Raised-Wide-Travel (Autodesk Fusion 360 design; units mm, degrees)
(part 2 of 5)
work_plane "WorkPlane28" AlongDistance 15.3 ExtraOffset 0
sketch "Fill former insert location (3)" plane through (15.3, 0, 0) normal (1, 0, 0) x axis (0, 0, -1)
  circle C1 centre (-52, -51) radius 2.01
extrude "Extrude28" add sketch "Fill former insert location (3)" along normal blind 8.7
work_plane "WorkPlane27" AlongDistance -36 ExtraOffset 0
sketch "Fill former plate mounting hole (1)" plane through (-36, 0, 0) normal (1, 0, 0) x axis (0, 0, -1)
  circle C1 centre (-52, -51) radius 1.71
extrude "Extrude27" add sketch "Fill former plate mounting hole (1)" along normal blind 12
work_plane "WorkPlane26" AlongDistance 24 ExtraOffset 0
sketch "Fill former plate mounting hole (1)" plane through (24, 0, 0) normal (1, 0, 0) x axis (0, 0, -1)
  circle C1 centre (-52, -51) radius 1.71
extrude "Extrude26" add sketch "Fill former plate mounting hole (1)" along normal blind 12
work_plane "WorkPlane29" AlongDistance -24.1 ExtraOffset 0
sketch "Relocated insert with cam-side retaining wall" plane through (-24.1, 0, 0) normal (1, 0, 0) x axis (0, 0, -1)
  circle C1 centre (-53.5, -62) radius 2
extrude "Extrude29" cut sketch "Relocated insert with cam-side retaining wall" along normal blind 8.9
work_plane "WorkPlane30" AlongDistance 15.3 ExtraOffset 0
sketch "Relocated insert with cam-side retaining wall (1)" plane through (15.3, 0, 0) normal (1, 0, 0) x axis (0, 0, -1)
  circle C1 centre (-53.5, -62) radius 2
extrude "Extrude30" cut sketch "Relocated insert with cam-side retaining wall (1)" along normal blind 8.9
work_plane "WorkPlane28" AlongDistance -36.1 ExtraOffset 0
sketch "Relocated mount above rail counterbore" plane through (-36.1, 0, 0) normal (1, 0, 0) x axis (0, 0, -1)
  circle C1 centre (-53.5, -62) radius 1.7
extrude "Extrude28" cut sketch "Relocated mount above rail counterbore" along normal blind 12.2
work_plane "WorkPlane27" AlongDistance 23.9 ExtraOffset 0
sketch "Relocated mount above rail counterbore" plane through (23.9, 0, 0) normal (1, 0, 0) x axis (0, 0, -1)
  circle C1 centre (-53.5, -62) radius 1.7
extrude "Extrude27" cut sketch "Relocated mount above rail counterbore" along normal blind 12.2
work_plane "WorkPlane31" AlongDistance -24.1 ExtraOffset 0
sketch "Relocated insert with cam-side retaining wall (2)" plane through (-24.1, 0, 0) normal (1, 0, 0) x axis (0, 0, -1)
  circle C1 centre (-53.5, -54) radius 2
extrude "Extrude31" cut sketch "Relocated insert with cam-side retaining wall (2)" along normal blind 8.9
work_plane "WorkPlane32" AlongDistance 15.3 ExtraOffset 0
sketch "Relocated insert with cam-side retaining wall (3)" plane through (15.3, 0, 0) normal (1, 0, 0) x axis (0, 0, -1)
  circle C1 centre (-53.5, -54) radius 2
extrude "Extrude32" cut sketch "Relocated insert with cam-side retaining wall (3)" along normal blind 8.9
work_plane "WorkPlane29" AlongDistance -36.1 ExtraOffset 0
sketch "Relocated mount above rail counterbore (1)" plane through (-36.1, 0, 0) normal (1, 0, 0) x axis (0, 0, -1)
  circle C1 centre (-53.5, -54) radius 1.7
extrude "Extrude29" cut sketch "Relocated mount above rail counterbore (1)" along normal blind 12.2
work_plane "WorkPlane28" AlongDistance 23.9 ExtraOffset 0
sketch "Relocated mount above rail counterbore (1)" plane through (23.9, 0, 0) normal (1, 0, 0) x axis (0, 0, -1)
  circle C1 centre (-53.5, -54) radius 1.7
extrude "Extrude28" cut sketch "Relocated mount above rail counterbore (1)" along normal blind 12.2
work_plane "WorkPlane33" AlongDistance 51.9 ExtraOffset 0
sketch "Continue adjuster bore through roof" plane through (0, 0, 51.9) normal (0, 0, 1) x axis (1, 0, 0)
  circle C1 centre (12, -55) radius 2.2
extrude "Extrude33" cut sketch "Continue adjuster bore through roof" along normal blind 7.2
work_plane "WorkPlane34" AlongDistance 51.9 ExtraOffset 0
sketch "Continue guide bore through roof" plane through (0, 0, 51.9) normal (0, 0, 1) x axis (1, 0, 0)
  circle C1 centre (5, -55) radius 1.7
extrude "Extrude34" cut sketch "Continue guide bore through roof" along normal blind 7.2
work_plane "WorkPlane35" AlongDistance 51.9 ExtraOffset 0
sketch "Continue guide bore through roof (1)" plane through (0, 0, 51.9) normal (0, 0, 1) x axis (1, 0, 0)
  circle C1 centre (19, -55) radius 1.7
extrude "Extrude35" cut sketch "Continue guide bore through roof (1)" along normal blind 7.2
work_plane "WorkPlane36" AlongDistance -24.1 ExtraOffset 0
sketch "Restore cam envelope after pocket repair" plane through (-24.1, 0, 0) normal (1, 0, 0) x axis (0, 0, -1)
  circle C1 centre (-65, 0) radius 51
extrude "Extrude36" cut sketch "Restore cam envelope after pocket repair" along normal blind 48.2
work_plane "WorkPlane30" AlongDistance -76 ExtraOffset 0
sketch "Preserve rail shank passage" plane through (0, -76, 0) normal (0, 1, 0) x axis (1, 0, 0)
  circle C1 centre (-30, -45) radius 2.7
work_plane "WorkPlane31" AlongDistance 54 ExtraOffset 0
sketch "Preserve rail shank passage (1)" plane through (0, 54, 0) normal (0, 1, 0) x axis (1, 0, 0)
  circle C1 centre (-30, -45) radius 2.7
work_plane "WorkPlane32" AlongDistance -55 ExtraOffset 0
sketch "Preserve rail head passage" plane through (0, -55, 0) normal (0, 1, 0) x axis (1, 0, 0)
  circle C1 centre (-30, -45) radius 5.3
extrude "Extrude32" cut sketch "Preserve rail head passage" along normal blind 12
work_plane "WorkPlane33" AlongDistance 43 ExtraOffset 0
sketch "Preserve rail head passage (1)" plane through (0, 43, 0) normal (0, 1, 0) x axis (1, 0, 0)
  circle C1 centre (-30, -45) radius 5.3
work_plane "WorkPlane29" AlongDistance -76 ExtraOffset 0
sketch "Preserve rail shank passage" plane through (0, -76, 0) normal (0, 1, 0) x axis (1, 0, 0)
  circle C1 centre (30, -45) radius 2.7
work_plane "WorkPlane30" AlongDistance 54 ExtraOffset 0
sketch "Preserve rail shank passage (1)" plane through (0, 54, 0) normal (0, 1, 0) x axis (1, 0, 0)
  circle C1 centre (30, -45) radius 2.7
work_plane "WorkPlane31" AlongDistance -55 ExtraOffset 0
sketch "Preserve rail head passage" plane through (0, -55, 0) normal (0, 1, 0) x axis (1, 0, 0)
  circle C1 centre (30, -45) radius 5.3
extrude "Extrude31" cut sketch "Preserve rail head passage" along normal blind 12
work_plane "WorkPlane32" AlongDistance 43 ExtraOffset 0
sketch "Preserve rail head passage (1)" plane through (0, 43, 0) normal (0, 1, 0) x axis (1, 0, 0)
  circle C1 centre (30, -45) radius 5.3
work_plane "WorkPlane16" AlongDistance -5 ExtraOffset 0
sketch "Flat washer seat for sensor-drive shaft clamp" plane through (-5, 0, 0) normal (1, 0, 0) x axis (0, 0, -1)
  line L1 (-60, 22) -> (-60, 20)
  line L2 (-70, 22) -> (-60, 22)
  line L3 (-70, 20) -> (-70, 22)
  line L4 (-60, 20) -> (-70, 20)
extrude "Extrude16" add sketch "Flat washer seat for sensor-drive shaft clamp" along normal blind 10
work_plane "WorkPlane17" AlongDistance 6.4 ExtraOffset 0
sketch "Radial screw onto printed shaft D flat" plane through (0, 6.4, 0) normal (0, 1, 0) x axis (1, 0, 0)
  circle C1 centre (0, -65) radius 1.7
extrude "Extrude17" cut sketch "Radial screw onto printed shaft D flat" along normal blind 15.7
work_plane "WorkPlane18" AlongDistance 15.2 ExtraOffset 0
sketch "M3 heatset pocket for rotor clamp" plane through (0, 15.2, 0) normal (0, 1, 0) x axis (1, 0, 0)
  circle C1 centre (0, -65) radius 2
extrude "Extrude18" cut sketch "M3 heatset pocket for rotor clamp" along normal blind 6.9
work_plane "WorkPlane37" AlongDistance -24 ExtraOffset 0
sketch "Extend reaction block into free rail bay" plane through (-24, 0, 0) normal (1, 0, 0) x axis (0, 0, -1)
  line L1 (-38, -66) -> (-38, -74)
  line L2 (-59, -66) -> (-38, -66)
  line L3 (-59, -74) -> (-59, -66)
  line L4 (-38, -74) -> (-59, -74)
extrude "Extrude37" add sketch "Extend reaction block into free rail bay" along normal blind 48
work_plane "WorkPlane38" AlongDistance -24 ExtraOffset 0
sketch "Close mounting bore that crossed cup guide" plane through (-24, 0, 0) normal (1, 0, 0) x axis (0, 0, -1)
  circle C1 centre (-53.5, -54) radius 2.01
extrude "Extrude38" add sketch "Close mounting bore that crossed cup guide" along normal blind 8.7
work_plane "WorkPlane39" AlongDistance -24.1 ExtraOffset 0
sketch "Outer mounting row clear of guide" plane through (-24.1, 0, 0) normal (1, 0, 0) x axis (0, 0, -1)
  circle C1 centre (-53.5, -70) radius 2
extrude "Extrude39" cut sketch "Outer mounting row clear of guide" along normal blind 8.9
work_plane "WorkPlane40" AlongDistance 15.3 ExtraOffset 0
sketch "Close mounting bore that crossed cup guide (1)" plane through (15.3, 0, 0) normal (1, 0, 0) x axis (0, 0, -1)
  circle C1 centre (-53.5, -54) radius 2.01
extrude "Extrude40" add sketch "Close mounting bore that crossed cup guide (1)" along normal blind 8.7
work_plane "WorkPlane41" AlongDistance 15.2 ExtraOffset 0
sketch "Outer mounting row clear of guide (1)" plane through (15.2, 0, 0) normal (1, 0, 0) x axis (0, 0, -1)
  circle C1 centre (-53.5, -70) radius 2
extrude "Extrude41" cut sketch "Outer mounting row clear of guide (1)" along normal blind 8.9
work_plane "WorkPlane34" AlongDistance -36 ExtraOffset 0
sketch "Close former inner mounting hole" plane through (-36, 0, 0) normal (1, 0, 0) x axis (0, 0, -1)
  circle C1 centre (-53.5, -54) radius 1.71
extrude "Extrude34" add sketch "Close former inner mounting hole" along normal blind 12
work_plane "WorkPlane35" AlongDistance -36.1 ExtraOffset 0
sketch "Matched outer mounting row" plane through (-36.1, 0, 0) normal (1, 0, 0) x axis (0, 0, -1)
  circle C1 centre (-53.5, -70) radius 1.7
extrude "Extrude35" cut sketch "Matched outer mounting row" along normal blind 12.2
work_plane "WorkPlane33" AlongDistance 24 ExtraOffset 0
sketch "Close former inner mounting hole" plane through (24, 0, 0) normal (1, 0, 0) x axis (0, 0, -1)
  circle C1 centre (-53.5, -54) radius 1.71
extrude "Extrude33" add sketch "Close former inner mounting hole" along normal blind 12
work_plane "WorkPlane34" AlongDistance 23.9 ExtraOffset 0
sketch "Matched outer mounting row" plane through (23.9, 0, 0) normal (1, 0, 0) x axis (0, 0, -1)
  circle C1 centre (-53.5, -70) radius 1.7
extrude "Extrude34" cut sketch "Matched outer mounting row" along normal blind 12.2
work_plane "WorkPlane42" AlongDistance 37.9 ExtraOffset 0
sketch "Restore separate cup guide bore" plane through (0, 0, 37.9) normal (0, 0, 1) x axis (1, 0, 0)
  circle C1 centre (5, -55) radius 1.7
work_plane "WorkPlane43" AlongDistance 37.9 ExtraOffset 0
sketch "Restore separate cup guide bore (1)" plane through (0, 0, 37.9) normal (0, 0, 1) x axis (1, 0, 0)
  circle C1 centre (19, -55) radius 1.7
extrude "Extrude43" cut sketch "Restore separate cup guide bore (1)" along normal blind 21.2
work_plane "WorkPlane44" AlongDistance -24.1 ExtraOffset 0
sketch "Preserve cam envelope" plane through (-24.1, 0, 0) normal (1, 0, 0) x axis (0, 0, -1)
  circle C1 centre (-65, 0) radius 51
work_plane "WorkPlane36" AlongDistance -55 ExtraOffset 0
sketch "Close inaccessible rail head pocket" plane through (0, -55, 0) normal (0, 1, 0) x axis (1, 0, 0)
  circle C1 centre (-30, -45) radius 5.31
extrude "Extrude36" add sketch "Close inaccessible rail head pocket" along normal blind 12
work_plane "WorkPlane37" AlongDistance 43 ExtraOffset 0
sketch "Close inaccessible rail head pocket (1)" plane through (0, 43, 0) normal (0, 1, 0) x axis (1, 0, 0)
  circle C1 centre (-30, -45) radius 5.31
extrude "Extrude37" add sketch "Close inaccessible rail head pocket (1)" along normal blind 12
work_plane "WorkPlane38" AlongDistance -75 ExtraOffset 0
sketch "Close obsolete side rail bore" plane through (0, -75, 0) normal (0, 1, 0) x axis (1, 0, 0)
  circle C1 centre (-30, -45) radius 2.71
extrude "Extrude38" add sketch "Close obsolete side rail bore" along normal blind 20
work_plane "WorkPlane39" AlongDistance 55 ExtraOffset 0
sketch "Close obsolete side rail bore (1)" plane through (0, 55, 0) normal (0, 1, 0) x axis (1, 0, 0)
  circle C1 centre (-30, -45) radius 2.71
extrude "Extrude39" add sketch "Close obsolete side rail bore (1)" along normal blind 20
work_plane "WorkPlane40" AlongDistance -36 ExtraOffset 0
sketch "Top-access 2020 mounting flange" plane through (-36, 0, 0) normal (1, 0, 0) x axis (0, 0, -1)
  line L1 (-55, -70) -> (-55, -95)
  line L2 (-63, -70) -> (-55, -70)
  line L3 (-63, -95) -> (-63, -70)
  line L4 (-55, -95) -> (-63, -95)
extrude "Extrude40" add sketch "Top-access 2020 mounting flange" along normal blind 12
work_plane "WorkPlane41" AlongDistance -36 ExtraOffset 0
sketch "Mount root triangular reinforcement" plane through (-36, 0, 0) normal (1, 0, 0) x axis (0, 0, -1)
  line L1 (-56, -63) -> (-56, -70)
  line L2 (-63, -70) -> (-56, -63)
  line L3 (-56, -70) -> (-63, -70)
extrude "Extrude41" add sketch "Mount root triangular reinforcement" along normal blind 12
work_plane "WorkPlane42" AlongDistance 54.9 ExtraOffset 0
sketch "Vertical M5 rail mounting bore" plane through (0, 0, 54.9) normal (0, 0, 1) x axis (1, 0, 0)
  circle C1 centre (-30, -85) radius 2.7
extrude "Extrude42" cut sketch "Vertical M5 rail mounting bore" along normal blind 8.2
work_plane "WorkPlane43" AlongDistance -36 ExtraOffset 0
sketch "Top-access 2020 mounting flange (1)" plane through (-36, 0, 0) normal (1, 0, 0) x axis (0, 0, -1)
  line L1 (-55, 95) -> (-55, 70)
  line L2 (-63, 95) -> (-55, 95)
  line L3 (-63, 70) -> (-63, 95)
  line L4 (-55, 70) -> (-63, 70)
extrude "Extrude43" add sketch "Top-access 2020 mounting flange (1)" along normal blind 12
work_plane "WorkPlane44" AlongDistance -36 ExtraOffset 0
sketch "Mount root triangular reinforcement (1)" plane through (-36, 0, 0) normal (1, 0, 0) x axis (0, 0, -1)
  line L1 (-56, 70) -> (-56, 63)
  line L2 (-63, 70) -> (-56, 70)
  line L3 (-56, 63) -> (-63, 70)
extrude "Extrude44" add sketch "Mount root triangular reinforcement (1)" along normal blind 12
work_plane "WorkPlane45" AlongDistance 54.9 ExtraOffset 0
sketch "Vertical M5 rail mounting bore (1)" plane through (0, 0, 54.9) normal (0, 0, 1) x axis (1, 0, 0)
  circle C1 centre (-30, 85) radius 2.7
extrude "Extrude45" cut sketch "Vertical M5 rail mounting bore (1)" along normal blind 8.2
work_plane "WorkPlane46" AlongDistance -36 ExtraOffset 0
sketch "Close old M5 pivot clearance" plane through (-36, 0, 0) normal (1, 0, 0) x axis (0, 0, -1)
  circle C1 centre (-12, -35) radius 2.71
extrude "Extrude46" add sketch "Close old M5 pivot clearance" along normal blind 12
work_plane "WorkPlane47" AlongDistance -36.1 ExtraOffset 0
sketch "M3 follower pivot clearance" plane through (-36.1, 0, 0) normal (1, 0, 0) x axis (0, 0, -1)
  circle C1 centre (-12, -35) radius 1.7
extrude "Extrude47" cut sketch "M3 follower pivot clearance" along normal blind 12.2
work_plane "WorkPlane35" AlongDistance -55 ExtraOffset 0
sketch "Close inaccessible rail head pocket" plane through (0, -55, 0) normal (0, 1, 0) x axis (1, 0, 0)
  circle C1 centre (30, -45) radius 5.31
extrude "Extrude35" add sketch "Close inaccessible rail head pocket" along normal blind 12
work_plane "WorkPlane36" AlongDistance 43 ExtraOffset 0
sketch "Close inaccessible rail head pocket (1)" plane through (0, 43, 0) normal (0, 1, 0) x axis (1, 0, 0)
  circle C1 centre (30, -45) radius 5.31
extrude "Extrude36" add sketch "Close inaccessible rail head pocket (1)" along normal blind 12
work_plane "WorkPlane37" AlongDistance -75 ExtraOffset 0
sketch "Close obsolete side rail bore" plane through (0, -75, 0) normal (0, 1, 0) x axis (1, 0, 0)
  circle C1 centre (30, -45) radius 2.71
extrude "Extrude37" add sketch "Close obsolete side rail bore" along normal blind 20
work_plane "WorkPlane38" AlongDistance 55 ExtraOffset 0
sketch "Close obsolete side rail bore (1)" plane through (0, 55, 0) normal (0, 1, 0) x axis (1, 0, 0)
  circle C1 centre (30, -45) radius 2.71
extrude "Extrude38" add sketch "Close obsolete side rail bore (1)" along normal blind 20
work_plane "WorkPlane39" AlongDistance 24 ExtraOffset 0
sketch "Top-access 2020 mounting flange" plane through (24, 0, 0) normal (1, 0, 0) x axis (0, 0, -1)
  line L1 (-55, -70) -> (-55, -95)
  line L2 (-63, -70) -> (-55, -70)
  line L3 (-63, -95) -> (-63, -70)
  line L4 (-55, -95) -> (-63, -95)
extrude "Extrude39" add sketch "Top-access 2020 mounting flange" along normal blind 12
work_plane "WorkPlane40" AlongDistance 24 ExtraOffset 0
sketch "Mount root triangular reinforcement" plane through (24, 0, 0) normal (1, 0, 0) x axis (0, 0, -1)
  line L1 (-56, -63) -> (-56, -70)
  line L2 (-63, -70) -> (-56, -63)
  line L3 (-56, -70) -> (-63, -70)
extrude "Extrude40" add sketch "Mount root triangular reinforcement" along normal blind 12
work_plane "WorkPlane41" AlongDistance 54.9 ExtraOffset 0
sketch "Vertical M5 rail mounting bore" plane through (0, 0, 54.9) normal (0, 0, 1) x axis (1, 0, 0)
  circle C1 centre (30, -85) radius 2.7
extrude "Extrude41" cut sketch "Vertical M5 rail mounting bore" along normal blind 8.2
work_plane "WorkPlane42" AlongDistance 24 ExtraOffset 0
sketch "Top-access 2020 mounting flange (1)" plane through (24, 0, 0) normal (1, 0, 0) x axis (0, 0, -1)
  line L1 (-55, 95) -> (-55, 70)
  line L2 (-63, 95) -> (-55, 95)
  line L3 (-63, 70) -> (-63, 95)
  line L4 (-55, 70) -> (-63, 70)
extrude "Extrude42" add sketch "Top-access 2020 mounting flange (1)" along normal blind 12
work_plane "WorkPlane43" AlongDistance 24 ExtraOffset 0
sketch "Mount root triangular reinforcement (1)" plane through (24, 0, 0) normal (1, 0, 0) x axis (0, 0, -1)
  line L1 (-56, 70) -> (-56, 63)
  line L2 (-63, 70) -> (-56, 70)
  line L3 (-56, 63) -> (-63, 70)
extrude "Extrude43" add sketch "Mount root triangular reinforcement (1)" along normal blind 12
work_plane "WorkPlane44" AlongDistance 54.9 ExtraOffset 0
sketch "Vertical M5 rail mounting bore (1)" plane through (0, 0, 54.9) normal (0, 0, 1) x axis (1, 0, 0)
  circle C1 centre (30, 85) radius 2.7
extrude "Extrude44" cut sketch "Vertical M5 rail mounting bore (1)" along normal blind 8.2
work_plane "WorkPlane45" AlongDistance 24 ExtraOffset 0
sketch "Close old M5 pivot clearance" plane through (24, 0, 0) normal (1, 0, 0) x axis (0, 0, -1)
  circle C1 centre (-12, -35) radius 2.71
extrude "Extrude45" add sketch "Close old M5 pivot clearance" along normal blind 12
work_plane "WorkPlane46" AlongDistance 23.9 ExtraOffset 0
sketch "M3 follower pivot clearance" plane through (23.9, 0, 0) normal (1, 0, 0) x axis (0, 0, -1)
  circle C1 centre (-12, -35) radius 1.7
extrude "Extrude46" cut sketch "M3 follower pivot clearance" along normal blind 12.2
work_plane "WorkPlane47" AlongDistance 23.9 ExtraOffset 0
sketch "Restore cam service opening after obsolete bore closure" plane through (23.9, 0, 0) normal (1, 0, 0) x axis (0, 0, -1)
  line L1 (-42.2047, 46.7373) -> (-43.8497, 47.5044)
  line L2 (-40.5875, 45.9133) -> (-42.2047, 46.7373)
  line L3 (-39, 45.0333) -> (-40.5875, 45.9133)
  line L4 (-37.4442, 44.0985) -> (-39, 45.0333)
  line L5 (-35.922, 43.11) -> (-37.4442, 44.0985)
  line L6 (-34.4352, 42.0689) -> (-35.922, 43.11)
  line L7 (-32.9856, 40.9766) -> (-34.4352, 42.0689)
  line L8 (-31.575, 39.8343) -> (-32.9856, 40.9766)
  line L9 (-30.2052, 38.6435) -> (-31.575, 39.8343)
  line L10 (-28.8778, 37.4057) -> (-30.2052, 38.6435)
  line L11 (-27.5943, 36.1222) -> (-28.8778, 37.4057)
  line L12 (-26.3565, 34.7948) -> (-27.5943, 36.1222)
  line L13 (-25.1657, 33.425) -> (-26.3565, 34.7948)
  line L14 (-24.0234, 32.0144) -> (-25.1657, 33.425)
  line L15 (-22.9311, 30.5648) -> (-24.0234, 32.0144)
  line L16 (-21.89, 29.078) -> (-22.9311, 30.5648)
  line L17 (-20.9015, 27.5558) -> (-21.89, 29.078)
  line L18 (-19.9667, 26) -> (-20.9015, 27.5558)
  line L19 (-19.0867, 24.4125) -> (-19.9667, 26)
  line L20 (-18.2627, 22.7953) -> (-19.0867, 24.4125)
  line L21 (-17.4956, 21.1503) -> (-18.2627, 22.7953)
  line L22 (-16.7864, 19.4795) -> (-17.4956, 21.1503)
  line L23 (-16.136, 17.785) -> (-16.7864, 19.4795)
  line L24 (-15.5451, 16.0689) -> (-16.136, 17.785)
  line L25 (-15.0144, 14.3331) -> (-15.5451, 16.0689)
  line L26 (-14.5446, 12.5799) -> (-15.0144, 14.3331)
  line L27 (-14.1363, 10.8114) -> (-14.5446, 12.5799)
  line L28 (-13.79, 9.0297) -> (-14.1363, 10.8114)
  line L29 (-13.5061, 7.237) -> (-13.79, 9.0297)
  line L30 (-13.2849, 5.4355) -> (-13.5061, 7.237)
  line L31 (-13.1267, 3.6273) -> (-13.2849, 5.4355)
  line L32 (-13.0317, 1.8148) -> (-13.1267, 3.6273)
  line L33 (-13, 0) -> (-13.0317, 1.8148)
  line L34 (-13.0317, -1.8148) -> (-13, 0)
  line L35 (-13.1267, -3.6273) -> (-13.0317, -1.8148)
  line L36 (-13.2849, -5.4355) -> (-13.1267, -3.6273)
  line L37 (-13.5061, -7.237) -> (-13.2849, -5.4355)
  line L38 (-13.79, -9.0297) -> (-13.5061, -7.237)
  line L39 (-14.1363, -10.8114) -> (-13.79, -9.0297)
  line L40 (-14.5446, -12.5799) -> (-14.1363, -10.8114)
  line L41 (-15.0144, -14.3331) -> (-14.5446, -12.5799)
  line L42 (-15.5451, -16.0689) -> (-15.0144, -14.3331)
  line L43 (-16.136, -17.785) -> (-15.5451, -16.0689)
  line L44 (-16.7864, -19.4795) -> (-16.136, -17.785)
  line L45 (-17.4956, -21.1503) -> (-16.7864, -19.4795)
  line L46 (-18.2627, -22.7953) -> (-17.4956, -21.1503)
  line L47 (-19.0867, -24.4125) -> (-18.2627, -22.7953)
  line L48 (-19.9667, -26) -> (-19.0867, -24.4125)
  line L49 (-20.9015, -27.5558) -> (-19.9667, -26)
  line L50 (-21.89, -29.078) -> (-20.9015, -27.5558)
  line L51 (-22.9311, -30.5648) -> (-21.89, -29.078)
  line L52 (-24.0234, -32.0144) -> (-22.9311, -30.5648)
  line L53 (-25.1657, -33.425) -> (-24.0234, -32.0144)
  line L54 (-26.3565, -34.7948) -> (-25.1657, -33.425)
  line L55 (-27.5943, -36.1222) -> (-26.3565, -34.7948)
  line L56 (-28.8778, -37.4057) -> (-27.5943, -36.1222)
  line L57 (-30.2052, -38.6435) -> (-28.8778, -37.4057)
  line L58 (-31.575, -39.8343) -> (-30.2052, -38.6435)
  line L59 (-32.9856, -40.9766) -> (-31.575, -39.8343)
  line L60 (-34.4352, -42.0689) -> (-32.9856, -40.9766)
  line L61 (-35.922, -43.11) -> (-34.4352, -42.0689)
  line L62 (-37.4442, -44.0985) -> (-35.922, -43.11)
  line L63 (-39, -45.0333) -> (-37.4442, -44.0985)
  line L64 (-40.5875, -45.9133) -> (-39, -45.0333)
  line L65 (-42.2047, -46.7373) -> (-40.5875, -45.9133)
  line L66 (-43.8497, -47.5044) -> (-42.2047, -46.7373)
  line L67 (-54.4248, -23.7522) -> (-43.8497, -47.5044)
  line L68 (-53.6024, -23.3686) -> (-54.4248, -23.7522)
  line L69 (-52.7937, -22.9566) -> (-53.6024, -23.3686)
  line L70 (-52, -22.5167) -> (-52.7937, -22.9566)
  line L71 (-51.2221, -22.0493) -> (-52, -22.5167)
  line L72 (-50.461, -21.555) -> (-51.2221, -22.0493)
  line L73 (-49.7176, -21.0344) -> (-50.461, -21.555)
  line L74 (-48.9928, -20.4883) -> (-49.7176, -21.0344)
  line L75 (-48.2875, -19.9172) -> (-48.9928, -20.4883)
  line L76 (-47.6026, -19.3218) -> (-48.2875, -19.9172)
  line L77 (-46.9389, -18.7028) -> (-47.6026, -19.3218)
  line L78 (-46.2972, -18.0611) -> (-46.9389, -18.7028)
  line L79 (-45.6782, -17.3974) -> (-46.2972, -18.0611)
  line L80 (-45.0828, -16.7125) -> (-45.6782, -17.3974)
  line L81 (-44.5117, -16.0072) -> (-45.0828, -16.7125)
  line L82 (-43.9656, -15.2824) -> (-44.5117, -16.0072)
  line L83 (-43.445, -14.539) -> (-43.9656, -15.2824)
  line L84 (-42.9507, -13.7779) -> (-43.445, -14.539)
  line L85 (-42.4833, -13) -> (-42.9507, -13.7779)
  line L86 (-42.0434, -12.2063) -> (-42.4833, -13)
  line L87 (-41.6314, -11.3976) -> (-42.0434, -12.2063)
  line L88 (-41.2478, -10.5752) -> (-41.6314, -11.3976)
  line L89 (-40.8932, -9.7398) -> (-41.2478, -10.5752)
  line L90 (-40.568, -8.8925) -> (-40.8932, -9.7398)
  line L91 (-40.2725, -8.0344) -> (-40.568, -8.8925)
  line L92 (-40.0072, -7.1666) -> (-40.2725, -8.0344)
  line L93 (-39.7723, -6.29) -> (-40.0072, -7.1666)
  line L94 (-39.5682, -5.4057) -> (-39.7723, -6.29)
  line L95 (-39.395, -4.5149) -> (-39.5682, -5.4057)
  line L96 (-39.253, -3.6185) -> (-39.395, -4.5149)
  line L97 (-39.1424, -2.7177) -> (-39.253, -3.6185)
  line L98 (-39.0633, -1.8137) -> (-39.1424, -2.7177)
  line L99 (-39.0158, -0.9074) -> (-39.0633, -1.8137)
  line L100 (-39, 0) -> (-39.0158, -0.9074)
  line L101 (-39.0158, 0.9074) -> (-39, 0)
  line L102 (-39.0633, 1.8137) -> (-39.0158, 0.9074)
  line L103 (-39.1424, 2.7177) -> (-39.0633, 1.8137)
  line L104 (-39.253, 3.6185) -> (-39.1424, 2.7177)
  line L105 (-39.395, 4.5149) -> (-39.253, 3.6185)
  line L106 (-39.5682, 5.4057) -> (-39.395, 4.5149)
  line L107 (-39.7723, 6.29) -> (-39.5682, 5.4057)
  line L108 (-40.0072, 7.1666) -> (-39.7723, 6.29)
  line L109 (-40.2725, 8.0344) -> (-40.0072, 7.1666)
  line L110 (-40.568, 8.8925) -> (-40.2725, 8.0344)
  line L111 (-40.8932, 9.7398) -> (-40.568, 8.8925)
  line L112 (-41.2478, 10.5752) -> (-40.8932, 9.7398)
  line L113 (-41.6314, 11.3976) -> (-41.2478, 10.5752)
  line L114 (-42.0434, 12.2063) -> (-41.6314, 11.3976)
  line L115 (-42.4833, 13) -> (-42.0434, 12.2063)
  line L116 (-42.9507, 13.7779) -> (-42.4833, 13)
  line L117 (-43.445, 14.539) -> (-42.9507, 13.7779)
  line L118 (-43.9656, 15.2824) -> (-43.445, 14.539)
  line L119 (-44.5117, 16.0072) -> (-43.9656, 15.2824)
  line L120 (-45.0828, 16.7125) -> (-44.5117, 16.0072)
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extrude "Extrude47" cut sketch "Restore cam service opening after obsolete bore closure" along normal blind 12.2
work_plane "WorkPlane48" AlongDistance -15.4 ExtraOffset 0
sketch "Fill former M5 stop nut pocket" plane through (-15.4, 0, 0) normal (1, 0, 0) x axis (0, 0, -1)
  circle C1 centre (-79.6754, -33.9652) radius 4.9
work_plane "WorkPlane49" AlongDistance -36 ExtraOffset 0
sketch "Fill former M5 stop bore" plane through (-36, 0, 0) normal (1, 0, 0) x axis (0, 0, -1)
  circle C1 centre (-79.6754, -33.9652) radius 2.71
work_plane "WorkPlane50" AlongDistance -36.1 ExtraOffset 0
sketch "M3 stop reinforcement bore" plane through (-36.1, 0, 0) normal (1, 0, 0) x axis (0, 0, -1)
  circle C1 centre (-79.6754, -33.9652) radius 1.7
work_plane "WorkPlane51" AlongDistance -13.5 ExtraOffset 0
sketch "Captive M3 locknut stop pocket" plane through (-13.5, 0, 0) normal (1, 0, 0) x axis (0, 0, -1)
  line L1 (-82.5754, -32.2908) -> (-79.6754, -30.6165)
  line L2 (-82.5754, -35.6395) -> (-82.5754, -32.2908)
  line L3 (-79.6754, -37.3138) -> (-82.5754, -35.6395)
  line L4 (-76.7754, -35.6395) -> (-79.6754, -37.3138)
  line L5 (-76.7754, -32.2908) -> (-76.7754, -35.6395)
  line L6 (-79.6754, -30.6165) -> (-76.7754, -32.2908)
work_plane "WorkPlane52" AlongDistance -15.4 ExtraOffset 0
sketch "Fill former M5 stop nut pocket (1)" plane through (-15.4, 0, 0) normal (1, 0, 0) x axis (0, 0, -1)
  circle C1 centre (-79.6754, 33.9652) radius 4.9
work_plane "WorkPlane53" AlongDistance -36 ExtraOffset 0
sketch "Fill former M5 stop bore (1)" plane through (-36, 0, 0) normal (1, 0, 0) x axis (0, 0, -1)
  circle C1 centre (-79.6754, 33.9652) radius 2.71
work_plane "WorkPlane54" AlongDistance -36.1 ExtraOffset 0
sketch "M3 stop reinforcement bore (1)" plane through (-36.1, 0, 0) normal (1, 0, 0) x axis (0, 0, -1)
  circle C1 centre (-79.6754, 33.9652) radius 1.7
work_plane "WorkPlane55" AlongDistance -13.5 ExtraOffset 0
sketch "Captive M3 locknut stop pocket (1)" plane through (-13.5, 0, 0) normal (1, 0, 0) x axis (0, 0, -1)
  line L1 (-82.5754, 35.6395) -> (-79.6754, 37.3138)
  line L2 (-82.5754, 32.2908) -> (-82.5754, 35.6395)
  line L3 (-79.6754, 30.6165) -> (-82.5754, 32.2908)
  line L4 (-76.7754, 32.2908) -> (-79.6754, 30.6165)
  line L5 (-76.7754, 35.6395) -> (-76.7754, 32.2908)
  line L6 (-79.6754, 37.3138) -> (-76.7754, 35.6395)
work_plane "WorkPlane56" AlongDistance -17.5 ExtraOffset 0
sketch "Recess M3 locknut to keep bolt inside stop" plane through (-17.5, 0, 0) normal (1, 0, 0) x axis (0, 0, -1)
  line L1 (-82.5754, -32.2908) -> (-79.6754, -30.6165)
  line L2 (-82.5754, -35.6395) -> (-82.5754, -32.2908)
  line L3 (-79.6754, -37.3138) -> (-82.5754, -35.6395)
  line L4 (-76.7754, -35.6395) -> (-79.6754, -37.3138)
  line L5 (-76.7754, -32.2908) -> (-76.7754, -35.6395)
  line L6 (-79.6754, -30.6165) -> (-76.7754, -32.2908)
work_plane "WorkPlane57" AlongDistance -17.5 ExtraOffset 0
sketch "Recess M3 locknut to keep bolt inside stop (1)" plane through (-17.5, 0, 0) normal (1, 0, 0) x axis (0, 0, -1)
  line L1 (-82.5754, 35.6395) -> (-79.6754, 37.3138)
  line L2 (-82.5754, 32.2908) -> (-82.5754, 35.6395)
  line L3 (-79.6754, 30.6165) -> (-82.5754, 32.2908)
  line L4 (-76.7754, 32.2908) -> (-79.6754, 30.6165)
  line L5 (-76.7754, 35.6395) -> (-76.7754, 32.2908)
  line L6 (-79.6754, 37.3138) -> (-76.7754, 35.6395)
work_plane "WorkPlane6" AlongDistance -7.2 ExtraOffset 0
sketch "Upright socket roof 45 degrees" plane through (0, -7.2, 0) normal (0, 1, 0) x axis (1, 0, 0)
  line L1 (-7.2, -196) -> (0, -196)
  line L2 (0, -203.2) -> (-7.2, -196)
  line L3 (0, -196) -> (0, -203.2)
extrude "Extrude5" cut sketch "Upright socket roof 45 degrees" along normal blind 14.4
work_plane "WorkPlane8" AlongDistance -7.2 ExtraOffset 0
sketch "Upright socket roof 45 degrees" plane through (0, -7.2, 0) normal (0, 1, 0) x axis (1, 0, 0)
  line L1 (7.2, -196) -> (0, -196)
  line L2 (0, -203.2) -> (7.2, -196)
  line L3 (0, -196) -> (0, -203.2)
extrude "Extrude7" cut sketch "Upright socket roof 45 degrees" along normal blind 14.4
work_plane "WorkPlane58" AlongDistance -36 ExtraOffset 0
sketch "Stock M5x14 mounting seat Z64" plane through (-36, 0, 0) normal (1, 0, 0) x axis (0, 0, -1)
  line L1 (-63, -70) -> (-63, -95)
  line L2 (-64, -70) -> (-63, -70)
  line L3 (-64, -95) -> (-64, -70)
  line L4 (-63, -95) -> (-64, -95)
extrude "Extrude58" add sketch "Stock M5x14 mounting seat Z64" along normal blind 12
work_plane "WorkPlane59" AlongDistance 62.9 ExtraOffset 0
sketch "Continue rail clearance through new seat" plane through (0, 0, 62.9) normal (0, 0, 1) x axis (1, 0, 0)
  circle C1 centre (-30, -85) radius 2.7
extrude "Extrude59" cut sketch "Continue rail clearance through new seat" along normal blind 1.2
work_plane "WorkPlane60" AlongDistance -36 ExtraOffset 0
sketch "Stock M5x14 mounting seat Z64 (1)" plane through (-36, 0, 0) normal (1, 0, 0) x axis (0, 0, -1)
  line L1 (-63, 95) -> (-63, 70)
  line L2 (-64, 95) -> (-63, 95)
  line L3 (-64, 70) -> (-64, 95)
  line L4 (-63, 70) -> (-64, 70)
extrude "Extrude60" add sketch "Stock M5x14 mounting seat Z64 (1)" along normal blind 12
work_plane "WorkPlane61" AlongDistance 62.9 ExtraOffset 0
sketch "Continue rail clearance through new seat (1)" plane through (0, 0, 62.9) normal (0, 0, 1) x axis (1, 0, 0)
  circle C1 centre (-30, 85) radius 2.7
extrude "Extrude61" cut sketch "Continue rail clearance through new seat (1)" along normal blind 1.2
work_plane "WorkPlane62" AlongDistance -36 ExtraOffset 0
sketch "Close obsolete long pivot screw hole" plane through (-36, 0, 0) normal (1, 0, 0) x axis (0, 0, -1)
  circle C1 centre (-12, -35) radius 1.71
extrude "Extrude62" add sketch "Close obsolete long pivot screw hole" along normal blind 12
work_plane "WorkPlane63" AlongDistance -26 ExtraOffset 0
sketch "Blind captive printed pivot seat" plane through (-26, 0, 0) normal (1, 0, 0) x axis (0, 0, -1)
  circle C1 centre (-12, -35) radius 4.15
extrude "Extrude63" cut sketch "Blind captive printed pivot seat" along normal blind 2.1
work_plane "WorkPlane48" AlongDistance 24 ExtraOffset 0
sketch "Stock M5x14 mounting seat Z64" plane through (24, 0, 0) normal (1, 0, 0) x axis (0, 0, -1)
  line L1 (-63, -70) -> (-63, -95)
  line L2 (-64, -70) -> (-63, -70)
  line L3 (-64, -95) -> (-64, -70)
  line L4 (-63, -95) -> (-64, -95)
extrude "Extrude48" add sketch "Stock M5x14 mounting seat Z64" along normal blind 12
work_plane "WorkPlane49" AlongDistance 62.9 ExtraOffset 0
sketch "Continue rail clearance through new seat" plane through (0, 0, 62.9) normal (0, 0, 1) x axis (1, 0, 0)
  circle C1 centre (30, -85) radius 2.7
extrude "Extrude49" cut sketch "Continue rail clearance through new seat" along normal blind 1.2
work_plane "WorkPlane50" AlongDistance 24 ExtraOffset 0
sketch "Stock M5x14 mounting seat Z64 (1)" plane through (24, 0, 0) normal (1, 0, 0) x axis (0, 0, -1)
  line L1 (-63, 95) -> (-63, 70)
  line L2 (-64, 95) -> (-63, 95)
  line L3 (-64, 70) -> (-64, 95)
  line L4 (-63, 70) -> (-64, 70)
extrude "Extrude50" add sketch "Stock M5x14 mounting seat Z64 (1)" along normal blind 12
work_plane "WorkPlane51" AlongDistance 62.9 ExtraOffset 0
sketch "Continue rail clearance through new seat (1)" plane through (0, 0, 62.9) normal (0, 0, 1) x axis (1, 0, 0)
  circle C1 centre (30, 85) radius 2.7
extrude "Extrude51" cut sketch "Continue rail clearance through new seat (1)" along normal blind 1.2
work_plane "WorkPlane52" AlongDistance 24 ExtraOffset 0
sketch "Close obsolete long pivot screw hole" plane through (24, 0, 0) normal (1, 0, 0) x axis (0, 0, -1)
  circle C1 centre (-12, -35) radius 1.71
extrude "Extrude52" add sketch "Close obsolete long pivot screw hole" along normal blind 12
work_plane "WorkPlane53" AlongDistance 23.9 ExtraOffset 0
sketch "Blind captive printed pivot seat" plane through (23.9, 0, 0) normal (1, 0, 0) x axis (0, 0, -1)
  circle C1 centre (-12, -35) radius 4.15
extrude "Extrude53" cut sketch "Blind captive printed pivot seat" along normal blind 2.1
work_plane "WorkPlane1" AlongDistance -25.85 ExtraOffset 0
sketch "Captured axle 0.3 mm total end clearance" plane through (-25.85, 0, 0) normal (1, 0, 0) x axis (0, 0, -1)
  circle C1 centre (-12, -35) radius 4
extrude "Extrude1" new body sketch "Captured axle 0.3 mm total end clearance" along normal blind 51.7 bodies "P25 Captured printed pivot lower half"
work_plane "WorkPlane2" AlongDistance -26 ExtraOffset 0
sketch "Longitudinal flat print face" plane through (-26, 0, 0) normal (1, 0, 0) x axis (0, 0, -1)
  line L1 (-7, -30) -> (-7, -35)
  line L2 (-17, -30) -> (-7, -30)
  line L3 (-17, -35) -> (-17, -30)
  line L4 (-7, -35) -> (-17, -35)
extrude "Extrude2" cut sketch "Longitudinal flat print face" along normal blind 52
work_plane "WorkPlane1" AlongDistance -25.85 ExtraOffset 0
sketch "Captured axle 0.3 mm total end clearance" plane through (-25.85, 0, 0) normal (1, 0, 0) x axis (0, 0, -1)
  circle C1 centre (-12, -35) radius 4
extrude "Extrude1" new body sketch "Captured axle 0.3 mm total end clearance" along normal blind 51.7 bodies "P26 Captured printed pivot upper half"
work_plane "WorkPlane2" AlongDistance -26 ExtraOffset 0
sketch "Longitudinal flat print face" plane through (-26, 0, 0) normal (1, 0, 0) x axis (0, 0, -1)
  line L1 (-7, -35) -> (-7, -40)
  line L2 (-17, -35) -> (-7, -35)
  line L3 (-17, -40) -> (-17, -35)
  line L4 (-7, -40) -> (-17, -40)
extrude "Extrude2" cut sketch "Longitudinal flat print face" along normal blind 52
work_plane "WorkPlane9" AlongDistance 9 ExtraOffset 0
sketch "Recess for stocked M3x20 grip screw" plane through (9, 0, 0) normal (1, 0, 0) x axis (0, 0, -1)
  circle C1 centre (-180, 0) radius 3.1
extrude "Extrude8" cut sketch "Recess for stocked M3x20 grip screw" along normal blind 3.6
work_plane "WorkPlane1" AlongDistance -11 ExtraOffset 0
sketch "Grip M3x20 cap head 180" plane through (-11, 0, 0) normal (1, 0, 0) x axis (0, 0, -1)
  circle C1 centre (-180, 0) radius 1.5
extrude "Extrude1" new body sketch "Grip M3x20 cap head 180" along normal blind 20 bodies "HARDWARE Grip M3x20 cap head 180"
work_plane "WorkPlane2" AlongDistance 9 ExtraOffset 0
sketch "Button head" plane through (9, 0, 0) normal (1, 0, 0) x axis (0, 0, -1)
  circle C1 centre (-180, 0) radius 2.75
extrude "Extrude2" add sketch "Button head" along normal blind 3
work_plane "WorkPlane10" AlongDistance 9 ExtraOffset 0
sketch "Recess for stocked M3x20 grip screw (1)" plane through (9, 0, 0) normal (1, 0, 0) x axis (0, 0, -1)
  circle C1 centre (-190, 0) radius 3.1
extrude "Extrude9" cut sketch "Recess for stocked M3x20 grip screw (1)" along normal blind 3.6
work_plane "WorkPlane1" AlongDistance -11 ExtraOffset 0
sketch "Grip M3x20 cap head 190" plane through (-11, 0, 0) normal (1, 0, 0) x axis (0, 0, -1)
  circle C1 centre (-190, 0) radius 1.5
extrude "Extrude1" new body sketch "Grip M3x20 cap head 190" along normal blind 20 bodies "HARDWARE Grip M3x20 cap head 190"
work_plane "WorkPlane2" AlongDistance 9 ExtraOffset 0
sketch "Button head" plane through (9, 0, 0) normal (1, 0, 0) x axis (0, 0, -1)
  circle C1 centre (-190, 0) radius 2.75
extrude "Extrude2" add sketch "Button head" along normal blind 3
work_plane "WorkPlane64" AlongDistance -36.1 ExtraOffset 0
sketch "Stock M3x20 stop recessed cap head" plane through (-36.1, 0, 0) normal (1, 0, 0) x axis (0, 0, -1)
  circle C1 centre (-79.6754, -33.9652) radius 3.1
work_plane "WorkPlane65" AlongDistance -36.1 ExtraOffset 0
sketch "Stock M3x20 stop recessed cap head (1)" plane through (-36.1, 0, 0) normal (1, 0, 0) x axis (0, 0, -1)
  circle C1 centre (-79.6754, 33.9652) radius 3.1
work_plane "WorkPlane10" AlongDistance 7 ExtraOffset 0
sketch "Bearing inner race support pad" plane through (7, 0, 0) normal (1, 0, 0) x axis (0, 0, -1)
  circle C1 centre (-12, 0) radius 2.4
extrude "Extrude10" add sketch "Bearing inner race support pad" along normal blind 1
work_plane "WorkPlane11" AlongDistance 6.9 ExtraOffset 0
sketch "Preserve roller screw clearance" plane through (6.9, 0, 0) normal (1, 0, 0) x axis (0, 0, -1)
  circle C1 centre (-12, 0) radius 1.7
extrude "Extrude11" cut sketch "Preserve roller screw clearance" along normal blind 1.2
work_plane "WorkPlane12" AlongDistance 16 ExtraOffset 0
sketch "Bearing inner race support pad (1)" plane through (16, 0, 0) normal (1, 0, 0) x axis (0, 0, -1)
  circle C1 centre (-12, 0) radius 2.4
extrude "Extrude12" add sketch "Bearing inner race support pad (1)" along normal blind 1
work_plane "WorkPlane13" AlongDistance 15.9 ExtraOffset 0
sketch "Preserve roller screw clearance (1)" plane through (15.9, 0, 0) normal (1, 0, 0) x axis (0, 0, -1)
  circle C1 centre (-12, 0) radius 1.7
extrude "Extrude13" cut sketch "Preserve roller screw clearance (1)" along normal blind 1.2
work_plane "WorkPlane1" AlongDistance 8 ExtraOffset 0
sketch "Stock 623ZZ envelope 3x10x4" plane through (8, 0, 0) normal (1, 0, 0) x axis (0, 0, -1)
  circle C1 centre (-12, 0) radius 5
extrude "Extrude1" new body sketch "Stock 623ZZ envelope 3x10x4" along normal blind 4 bodies "HARDWARE 623ZZ roller bearing at 8"
work_plane "WorkPlane2" AlongDistance 7.9 ExtraOffset 0
sketch "Bearing inner race bore" plane through (7.9, 0, 0) normal (1, 0, 0) x axis (0, 0, -1)
  circle C1 centre (-12, 0) radius 1.5
extrude "Extrude2" cut sketch "Bearing inner race bore" along normal blind 4.2
work_plane "WorkPlane1" AlongDistance 12 ExtraOffset 0
sketch "Stock 623ZZ envelope 3x10x4" plane through (12, 0, 0) normal (1, 0, 0) x axis (0, 0, -1)
  circle C1 centre (-12, 0) radius 5
extrude "Extrude1" new body sketch "Stock 623ZZ envelope 3x10x4" along normal blind 4 bodies "HARDWARE 623ZZ roller bearing at 12"
work_plane "WorkPlane2" AlongDistance 11.9 ExtraOffset 0
sketch "Bearing inner race bore" plane through (11.9, 0, 0) normal (1, 0, 0) x axis (0, 0, -1)
  circle C1 centre (-12, 0) radius 1.5
extrude "Extrude2" cut sketch "Bearing inner race bore" along normal blind 4.2
work_plane "WorkPlane45" AlongDistance 38 ExtraOffset 0
sketch "Close former long guide bore" plane through (0, 0, 38) normal (0, 0, 1) x axis (1, 0, 0)
  circle C1 centre (5, -55) radius 1.71
extrude "Extrude45" add sketch "Close former long guide bore" along normal blind 21
work_plane "WorkPlane46" AlongDistance 38 ExtraOffset 0
sketch "Close former long guide bore (1)" plane through (0, 0, 38) normal (0, 0, 1) x axis (1, 0, 0)
  circle C1 centre (19, -55) radius 1.71
extrude "Extrude46" add sketch "Close former long guide bore (1)" along normal blind 21
work_plane "WorkPlane47" AlongDistance 38 ExtraOffset 0
sketch "Close obsolete M4 nut pocket" plane through (0, 0, 38) normal (0, 0, 1) x axis (1, 0, 0)
  line L1 (14.1362, -51.3) -> (16.2724, -55)
  line L2 (9.8638, -51.3) -> (14.1362, -51.3)
  line L3 (7.7276, -55) -> (9.8638, -51.3)
  line L4 (9.8638, -58.7) -> (7.7276, -55)
  line L5 (14.1362, -58.7) -> (9.8638, -58.7)
  line L6 (16.2724, -55) -> (14.1362, -58.7)
extrude "Extrude47" add sketch "Close obsolete M4 nut pocket" along normal blind 3.5
work_plane "WorkPlane48" AlongDistance 38 ExtraOffset 0
sketch "Close obsolete M4 adjuster passage" plane through (0, 0, 38) normal (0, 0, 1) x axis (1, 0, 0)
  circle C1 centre (12, -55) radius 2.21
extrude "Extrude48" add sketch "Close obsolete M4 adjuster passage" along normal blind 21
work_plane "WorkPlane49" AlongDistance 37.9 ExtraOffset 0
sketch "M3 preload adjuster passage" plane through (0, 0, 37.9) normal (0, 0, 1) x axis (1, 0, 0)
  circle C1 centre (12, -55) radius 1.7
extrude "Extrude49" cut sketch "M3 preload adjuster passage" along normal blind 21.2
work_plane "WorkPlane50" AlongDistance 37.9 ExtraOffset 0
sketch "M3 preload insert from spring side" plane through (0, 0, 37.9) normal (0, 0, 1) x axis (1, 0, 0)
  circle C1 centre (12, -55) radius 2
extrude "Extrude50" cut sketch "M3 preload insert from spring side" along normal blind 6.9
work_plane "WorkPlane51" AlongDistance 55 ExtraOffset 0
sketch "Recessed preload head and limiter access" plane through (0, 0, 55) normal (0, 0, 1) x axis (1, 0, 0)
  circle C1 centre (12, -55) radius 3.4
extrude "Extrude51" cut sketch "Recessed preload head and limiter access" along normal blind 4.1
work_plane "WorkPlane52" AlongDistance 37.9 ExtraOffset 0
sketch "Short guide M3 insert from underside" plane through (0, 0, 37.9) normal (0, 0, 1) x axis (1, 0, 0)
  circle C1 centre (4, -55) radius 2
extrude "Extrude52" cut sketch "Short guide M3 insert from underside" along normal blind 6.9
work_plane "WorkPlane1" AlongDistance 32 ExtraOffset 0
sketch "Short compression sleeve" plane through (0, 0, 32) normal (0, 0, 1) x axis (1, 0, 0)
  circle C1 centre (4, -55) radius 2.5
extrude "Extrude1" new body sketch "Short compression sleeve" along normal blind 6 bodies "P27 Printed guide sleeve 4"
work_plane "WorkPlane2" AlongDistance 31.9 ExtraOffset 0
sketch "Guide screw bore" plane through (0, 0, 31.9) normal (0, 0, 1) x axis (1, 0, 0)
  circle C1 centre (4, -55) radius 1.65
extrude "Extrude2" cut sketch "Guide screw bore" along normal blind 6.2
work_plane "WorkPlane1" AlongDistance 32 ExtraOffset 0
sketch "Cup guide M3x12 4" plane through (0, 0, 32) normal (0, 0, 1) x axis (1, 0, 0)
  circle C1 centre (4, -55) radius 1.5
extrude "Extrude1" new body sketch "Cup guide M3x12 4" along normal blind 12 bodies "HARDWARE Cup guide M3x12 4"
work_plane "WorkPlane2" AlongDistance 29 ExtraOffset 0
sketch "Button head" plane through (0, 0, 29) normal (0, 0, 1) x axis (1, 0, 0)
  circle C1 centre (4, -55) radius 2.75
extrude "Extrude2" add sketch "Button head" along normal blind 3
work_plane "WorkPlane53" AlongDistance 37.9 ExtraOffset 0
sketch "Short guide M3 insert from underside (1)" plane through (0, 0, 37.9) normal (0, 0, 1) x axis (1, 0, 0)
  circle C1 centre (20, -55) radius 2
extrude "Extrude53" cut sketch "Short guide M3 insert from underside (1)" along normal blind 6.9
work_plane "WorkPlane1" AlongDistance 32 ExtraOffset 0
sketch "Short compression sleeve" plane through (0, 0, 32) normal (0, 0, 1) x axis (1, 0, 0)
  circle C1 centre (20, -55) radius 2.5
extrude "Extrude1" new body sketch "Short compression sleeve" along normal blind 6 bodies "P27 Printed guide sleeve 20"
work_plane "WorkPlane2" AlongDistance 31.9 ExtraOffset 0
sketch "Guide screw bore" plane through (0, 0, 31.9) normal (0, 0, 1) x axis (1, 0, 0)
  circle C1 centre (20, -55) radius 1.65
extrude "Extrude2" cut sketch "Guide screw bore" along normal blind 6.2
work_plane "WorkPlane1" AlongDistance 32 ExtraOffset 0
sketch "Cup guide M3x12 20" plane through (0, 0, 32) normal (0, 0, 1) x axis (1, 0, 0)
  circle C1 centre (20, -55) radius 1.5
extrude "Extrude1" new body sketch "Cup guide M3x12 20" along normal blind 12 bodies "HARDWARE Cup guide M3x12 20"
work_plane "WorkPlane2" AlongDistance 29 ExtraOffset 0
sketch "Button head" plane through (0, 0, 29) normal (0, 0, 1) x axis (1, 0, 0)
  circle C1 centre (20, -55) radius 2.75
extrude "Extrude2" add sketch "Button head" along normal blind 3
work_plane "WorkPlane1" AlongDistance 0.2 ExtraOffset 0
sketch "Wide stock spring seat" plane through (0.2, 0, 0) normal (1, 0, 0) x axis (0, 0, -1)
  line L1 (-35, -49) -> (-35, -61)
  line L2 (-37, -49) -> (-35, -49)
  line L3 (-37, -61) -> (-37, -49)
  line L4 (-35, -61) -> (-37, -61)
extrude "Extrude1" new body sketch "Wide stock spring seat" along normal blind 23.6 bodies "P14 Captive spring cup for 9 mm spring"
work_plane "WorkPlane2" AlongDistance 29 ExtraOffset 0
sketch "Provisional 6 mm spring pilot" plane through (0, 0, 29) normal (0, 0, 1) x axis (1, 0, 0)
  circle C1 centre (12, -55) radius 3
extrude "Extrude2" add sketch "Provisional 6 mm spring pilot" along normal blind 6
work_plane "WorkPlane3" AlongDistance 34.9 ExtraOffset 0
sketch "Printed guide running clearance" plane through (0, 0, 34.9) normal (0, 0, 1) x axis (1, 0, 0)
  circle C1 centre (4, -55) radius 2.7
extrude "Extrude3" cut sketch "Printed guide running clearance" along normal blind 2.2
work_plane "WorkPlane4" AlongDistance 34.9 ExtraOffset 0
sketch "Printed guide running clearance (1)" plane through (0, 0, 34.9) normal (0, 0, 1) x axis (1, 0, 0)
  circle C1 centre (20, -55) radius 2.7
extrude "Extrude4" cut sketch "Printed guide running clearance (1)" along normal blind 2.2
work_plane "WorkPlane1" AlongDistance 55 ExtraOffset 0
sketch "Preserve one mm additional compression limit" plane through (0, 0, 55) normal (0, 0, 1) x axis (1, 0, 0)
  circle C1 centre (12, -55) radius 3.2
extrude "Extrude1" new body sketch "Preserve one mm additional compression limit" along normal blind 2 bodies "P15 Recessed preload limit collar 1 mm"
work_plane "WorkPlane2" AlongDistance 54.9 ExtraOffset 0
sketch "M3 adjuster clearance" plane through (0, 0, 54.9) normal (0, 0, 1) x axis (1, 0, 0)
  circle C1 centre (12, -55) radius 1.7
extrude "Extrude2" cut sketch "M3 adjuster clearance" along normal blind 2.2
work_plane "WorkPlane1" AlongDistance 37 ExtraOffset 0
sketch "Preload M3x20 cap head" plane through (0, 0, 37) normal (0, 0, 1) x axis (1, 0, 0)
  circle C1 centre (12, -55) radius 1.5
extrude "Extrude1" new body sketch "Preload M3x20 cap head" along normal blind 20 bodies "HARDWARE Preload M3x20 cap head"
work_plane "WorkPlane2" AlongDistance 57 ExtraOffset 0
sketch "Button head" plane through (0, 0, 57) normal (0, 0, 1) x axis (1, 0, 0)
  circle C1 centre (12, -55) radius 2.75
extrude "Extrude2" add sketch "Button head" along normal blind 3
work_plane "WorkPlane1" AlongDistance 18 ExtraOffset 0
sketch "Provisional stock spring installed envelope" plane through (0, 0, 18) normal (0, 0, 1) x axis (1, 0, 0)
  circle C1 centre (12, -55) radius 4.5
extrude "Extrude1" new body sketch "Provisional stock spring installed envelope" along normal blind 17 bodies "REFERENCE Stock spring OD9 wire1 free20 - rate and solid height assumed"
work_plane "WorkPlane2" AlongDistance 17.9 ExtraOffset 0
sketch "Stock spring nominal ID7" plane through (0, 0, 17.9) normal (0, 0, 1) x axis (1, 0, 0)
  circle C1 centre (12, -55) radius 3.5
extrude "Extrude2" cut sketch "Stock spring nominal ID7" along normal blind 17.2
work_plane "WorkPlane54" AlongDistance 36 ExtraOffset 0
sketch "Remove long sensor carriage supports" plane through (36, 0, 0) normal (1, 0, 0) x axis (0, 0, -1)
  line L1 (-46, 34) -> (-46, -34)
  line L2 (-84, 34) -> (-46, 34)
  line L3 (-84, -34) -> (-84, 34)
  line L4 (-46, -34) -> (-84, -34)
extrude "Extrude54" cut sketch "Remove long sensor carriage supports" along normal blind 44.1
work_plane "WorkPlane55" AlongDistance 36 ExtraOffset 0
sketch "Compact sensor support" plane through (36, 0, 0) normal (1, 0, 0) x axis (0, 0, -1)
  line L1 (-49, -18) -> (-49, -28)
  line L2 (-81, -18) -> (-49, -18)
  line L3 (-81, -28) -> (-81, -18)
  line L4 (-49, -28) -> (-81, -28)
extrude "Extrude55" add sketch "Compact sensor support" along normal blind 30.15
work_plane "WorkPlane56" AlongDistance -28.1 ExtraOffset 0
sketch "Compact carriage M3 insert" plane through (0, -28.1, 0) normal (0, 1, 0) x axis (1, 0, 0)
  circle C1 centre (60.15, -65) radius 2
extrude "Extrude56" cut sketch "Compact carriage M3 insert" along normal blind 6.8
work_plane "WorkPlane57" AlongDistance 36 ExtraOffset 0
sketch "Compact sensor support (1)" plane through (36, 0, 0) normal (1, 0, 0) x axis (0, 0, -1)
  line L1 (-49, 28) -> (-49, 18)
  line L2 (-81, 28) -> (-49, 28)
  line L3 (-81, 18) -> (-81, 28)
  line L4 (-49, 18) -> (-81, 18)
extrude "Extrude57" add sketch "Compact sensor support (1)" along normal blind 30.15
work_plane "WorkPlane58" AlongDistance 21.3 ExtraOffset 0
sketch "Compact carriage M3 insert (1)" plane through (0, 21.3, 0) normal (0, 1, 0) x axis (1, 0, 0)
  circle C1 centre (60.15, -65) radius 2
extrude "Extrude58" cut sketch "Compact carriage M3 insert (1)" along normal blind 6.8
work_plane "WorkPlane59" AlongDistance 36 ExtraOffset 0
sketch "Restore cam service path beneath compact rails" plane through (36, 0, 0) normal (1, 0, 0) x axis (0, 0, -1)
  line L1 (-48.9, -18) -> (-48.9, -28)
  line L2 (-56, -18) -> (-48.9, -18)
  line L3 (-56, -28) -> (-56, -18)
  line L4 (-48.9, -28) -> (-56, -28)
extrude "Extrude59" cut sketch "Restore cam service path beneath compact rails" along normal blind 30.25
work_plane "WorkPlane60" AlongDistance 36 ExtraOffset 0
sketch "Restore cam service path beneath compact rails (1)" plane through (36, 0, 0) normal (1, 0, 0) x axis (0, 0, -1)
  line L1 (-48.9, 28) -> (-48.9, 18)
  line L2 (-56, 28) -> (-48.9, 28)
  line L3 (-56, 18) -> (-56, 28)
  line L4 (-48.9, 18) -> (-56, 18)
extrude "Extrude60" cut sketch "Restore cam service path beneath compact rails (1)" along normal blind 30.25
work_plane "WorkPlane66" AlongDistance 54.9 ExtraOffset 0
